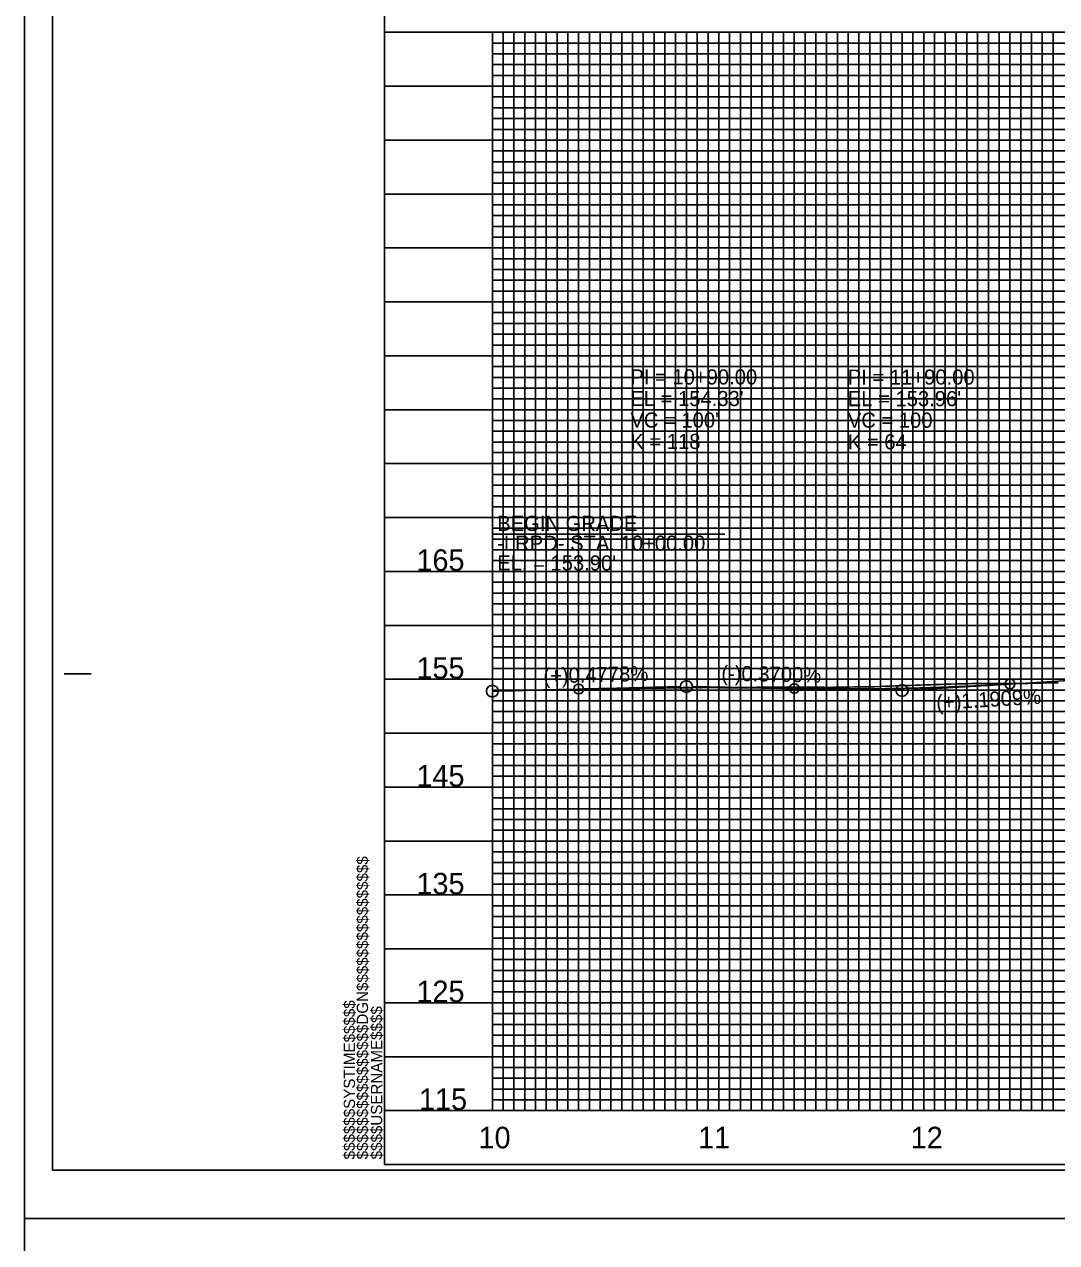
# Model space of a CAD drawing. Extents: x 573468 to 580768, y -57414 to -51768.
# Drawn here: x 578678 to 579157, y -54125 to -53560 of the extents above; entities that cross this region are included whole.
import ezdxf

# ---------------------------------------------------------------- set-up
doc = ezdxf.new("R2010")
doc.units = 0
for name, color, linetype in [('Exist Vertical Profile Ground Line', 7, 'Continuous'), ('Exist Vertical Profile Horizontal Axis Label Major', 7, 'Continuous'), ('Exist Vertical Profile Vertical Axis Label', 7, 'Continuous'), ('Prop Grid Mask', 7, 'Continuous'), ('Prop PFL Text', 7, 'Continuous'), ('Prop Vertical Profile Curve Label', 7, 'Continuous'), ('Prop Vertical Profile Grade', 7, 'Continuous'), ('Prop Vertical Profile Grade Label', 7, 'Continuous'), ('Prop VPI Label', 7, 'Continuous'), ('Sheet Cutting Line CELL', 7, 'Continuous'), ('Sheet DOT Grid CELL', 7, 'Continuous'), ('Sheet Layout Profile Border Port 2', 7, 'Continuous'), ('Sheet Plot Border Inside CELL', 7, 'Continuous'), ('Sheet Plot Border Outside CELL', 7, 'Continuous'), ('Sheet Profile CELL', 7, 'Continuous'), ('Sheet Profile Grid Major CELL', 7, 'Continuous'), ('Sheet Profile Grid Middle CELL', 7, 'Continuous'), ('Sheet Profile Grid Minor CELL', 7, 'Continuous')]:
    doc.layers.add(name, color=color, linetype=linetype)

msp = doc.modelspace()

# ---------------------------------------------------------------- linework, layer by layer
at = {"layer": 'Exist Vertical Profile Ground Line'}
for points in [[(578895.21, -53869.12), (578897.58, -53869.05), (578899.94, -53868.98), (578902.31, -53868.91), (578904.67, -53868.85), (578907.03, -53868.78), (578909.4, -53868.71), (578911.94, -53868.65), (578914.12, -53868.6), (578916.49, -53868.55), (578918.85, -53868.5), (578921.21, -53868.45), (578923.58, -53868.4), (578925.94, -53868.36), (578927.29, -53868.34), (578928.3, -53868.32), (578930.67, -53868.28), (578933.03, -53868.24), (578935.4, -53868.2), (578937.76, -53868.16), (578940.12, -53868.12), (578942.49, -53868.08), (578944.85, -53868.05), (578947.21, -53868.01), (578948.98, -53867.99), (578949.58, -53867.98), (578951.94, -53867.94), (578954.3, -53867.91), (578956.67, -53867.87), (578959.03, -53867.83), (578961.39, -53867.8), (578963.76, -53867.77), (578966.12, -53867.74), (578968.49, -53867.71), (578969.6, -53867.7), (578970.01, -53867.7), (578970.85, -53867.69), (578973.21, -53867.65), (578975.58, -53867.61), (578977.94, -53867.58), (578980.3, -53867.55), (578982.67, -53867.52), (578985.03, -53867.49), (578987.39, -53867.46), (578989.76, -53867.43), (578990.39, -53867.43), (578991.2, -53867.45), (578992.12, -53867.45), (578994.48, -53867.43), (578996.85, -53867.42), (578999.21, -53867.4), (579001.58, -53867.39), (579003.94, -53867.39), (579006.3, -53867.38), (579008.67, -53867.38), (579010.1, -53867.39), (579011.03, -53867.37), (579013.39, -53867.34), (579015.76, -53867.3), (579018.12, -53867.27), (579020.48, -53867.25), (579022.85, -53867.22), (579025.21, -53867.2), (579027.57, -53867.18), (579029.94, -53867.16), (579032.3, -53867.17), (579034.66, -53867.17), (579037.03, -53867.18), (579039.39, -53867.2), (579041.76, -53867.21), (579044.12, -53867.23), (579046.48, -53867.25), (579048.85, -53867.27), (579050.09, -53867.29), (579050.76, -53867.29), (579051.33, -53867.29), (579053.57, -53867.25), (579055.94, -53867.21), (579058.3, -53867.17), (579060.66, -53867.14), (579063.03, -53867.11), (579065.39, -53867.08), (579067.75, -53867.06), (579070.12, -53867.04), (579071.09, -53867.03), (579071.52, -53867.02), (579072.48, -53866.99), (579074.85, -53866.89), (579077.21, -53866.8), (579079.57, -53866.7), (579081.94, -53866.61), (579084.3, -53866.53), (579086.66, -53866.44), (579089.03, -53866.36), (579091.39, -53866.28), (579093.75, -53866.21), (579096.12, -53866.13), (579097.77, -53866.08), (579098.48, -53866.06), (579099.72, -53866.02), (579100.84, -53866.01)], [(579100.84, -53866.01), (579101.17, -53866), (579103.21, -53865.94), (579105.57, -53865.86), (579107.94, -53865.79), (579110.3, -53865.72), (579112.66, -53865.66), (579115.03, -53865.6), (579117.39, -53865.54), (579119.92, -53865.47), (579121.66, -53865.45), (579122.12, -53865.45), (579123.08, -53865.44), (579124.48, -53865.43), (579126.84, -53865.43), (579129.21, -53865.43), (579131.57, -53865.43), (579133.93, -53865.43), (579136.3, -53865.44), (579138.66, -53865.45), (579141.22, -53865.46), (579143.6, -53865.46), (579145.75, -53865.4), (579148.12, -53865.34), (579150.48, -53865.28), (579152.84, -53865.23), (579155.21, -53865.18), (579157.57, -53865.13)]]:
    msp.add_lwpolyline(points, dxfattribs=at)
at = {"layer": 'Prop Grid Mask'}
for points in [[(578945.21, -53713.55), (579045.21, -53713.55), (579045.21, -53763.55), (578945.21, -53763.55)], [(579045.21, -53713.55), (579145.21, -53713.55), (579145.21, -53763.55), (579045.21, -53763.55)]]:
    msp.add_lwpolyline(points, close=True, dxfattribs=at)
at = {"layer": 'Prop PFL Text'}
for q in [(579002.97, -53796.28), (578895.21, -53869.05)]:
    msp.add_line((578895.21, -53796.28), q, dxfattribs=at)
at = {"layer": 'Prop Vertical Profile Curve Label'}
for centre in [(579135.21, -53865.77), (578935.21, -53868.09), (579035.21, -53867.82), (579035.21, -53867.82)]:
    msp.add_circle(centre, 2.25, dxfattribs=at)
at = {"layer": 'Prop Vertical Profile Grade'}
for p, q in [((579135.21, -53865.77), (579195.21, -53862.2)), ((578895.21, -53869.05), (578935.21, -53868.09))]:
    msp.add_line(p, q, dxfattribs=at)
for points in [[(578935.21, -53868.09), (578937.21, -53868.05), (578939.21, -53868), (578941.21, -53867.96), (578943.21, -53867.92), (578945.21, -53867.88), (578947.21, -53867.84), (578949.21, -53867.8), (578951.21, -53867.77), (578953.21, -53867.73), (578955.21, -53867.7), (578957.21, -53867.67), (578959.21, -53867.64), (578961.21, -53867.62), (578963.21, -53867.59), (578965.21, -53867.57), (578967.21, -53867.55), (578969.21, -53867.53), (578971.21, -53867.51), (578973.21, -53867.49), (578975.21, -53867.48), (578977.21, -53867.46), (578979.21, -53867.45), (578981.21, -53867.44), (578983.21, -53867.44), (578985.21, -53867.43), (578987.21, -53867.42), (578989.21, -53867.42), (578991.21, -53867.42), (578993.21, -53867.42), (578995.21, -53867.42), (578997.21, -53867.43), (578999.21, -53867.43), (579001.21, -53867.44), (579003.21, -53867.45), (579005.21, -53867.46), (579007.21, -53867.47), (579009.21, -53867.49), (579011.21, -53867.5), (579013.21, -53867.52), (579015.21, -53867.54), (579017.21, -53867.56), (579019.21, -53867.58), (579021.21, -53867.61), (579023.21, -53867.63), (579025.21, -53867.66), (579027.21, -53867.69), (579029.21, -53867.72), (579031.21, -53867.75), (579033.21, -53867.79), (579035.21, -53867.82)], [(579035.21, -53867.82), (579037.21, -53867.86), (579039.21, -53867.89), (579041.21, -53867.92), (579043.21, -53867.95), (579045.21, -53867.97), (579047.21, -53867.99), (579049.21, -53868.01), (579051.21, -53868.02), (579053.21, -53868.03), (579055.21, -53868.04), (579057.21, -53868.04), (579059.21, -53868.04), (579061.21, -53868.04), (579063.21, -53868.04), (579065.21, -53868.03), (579067.21, -53868.02), (579069.21, -53868), (579071.21, -53867.98), (579073.21, -53867.96), (579075.21, -53867.94), (579077.21, -53867.91), (579079.21, -53867.88), (579081.21, -53867.85), (579083.21, -53867.81), (579085.21, -53867.77), (579087.21, -53867.73), (579089.21, -53867.69), (579091.21, -53867.64), (579093.21, -53867.58), (579095.21, -53867.53), (579097.21, -53867.47), (579099.21, -53867.41), (579101.21, -53867.35), (579103.21, -53867.28), (579105.21, -53867.21), (579107.21, -53867.13), (579109.21, -53867.06), (579111.21, -53866.98), (579113.21, -53866.89), (579115.21, -53866.81), (579117.21, -53866.72), (579119.21, -53866.63), (579121.21, -53866.53), (579123.21, -53866.43), (579125.21, -53866.33), (579127.21, -53866.22), (579129.21, -53866.12), (579131.21, -53866), (579133.21, -53865.89), (579135.21, -53865.77)]]:
    msp.add_spline(points, degree=3, dxfattribs=at)
at = {"layer": 'Prop VPI Label'}
for p, q in [((578935.21, -53868.09), (578982.47, -53866.97)), ((579035.21, -53867.82), (578987.96, -53866.95)), ((579035.21, -53867.82), (579082.47, -53868.7)), ((579135.21, -53865.77), (579087.96, -53868.59))]:
    msp.add_line(p, q, dxfattribs=at)
for centre in [(578895.21, -53869.05), (578985.21, -53866.9), (579085.21, -53868.75)]:
    msp.add_circle(centre, 2.75, dxfattribs=at)
at = {"layer": 'Sheet Cutting Line CELL'}
for p, q in [((578678.21, -53013.55), (578678.21, -54113.55)), ((578678.21, -54113.55), (580362.21, -54113.55)), ((580362.21, -54113.55), (578678.21, -54113.55)), ((578678.21, -54113.55), (578678.21, -55213.55))]:
    msp.add_line(p, q, dxfattribs=at)
at = {"layer": 'Sheet DOT Grid CELL'}
for p, q in [((578845.21, -53563.55), (580345.1, -53563.55)), ((578895.21, -53563.55), (578895.21, -54063.55)), ((578945.21, -53563.55), (578945.21, -54063.55)), ((578995.21, -53563.55), (578995.21, -54063.55)), ((579045.21, -53563.55), (579045.21, -54063.55)), ((579095.21, -53563.55), (579095.21, -54063.55)), ((579145.21, -53563.55), (579145.21, -54063.55)), ((578845.21, -53613.55), (580345.1, -53613.55)), ((578845.21, -53663.55), (580345.1, -53663.55)), ((578845.21, -53713.55), (580345.1, -53713.55)), ((578845.21, -53763.55), (580345.1, -53763.55)), ((578845.21, -53813.55), (580345.1, -53813.55)), ((578845.21, -53863.55), (580345.1, -53863.55)), ((578845.21, -53913.55), (580345.1, -53913.55)), ((578845.21, -53963.55), (580345.1, -53963.55)), ((578845.21, -54013.55), (580345.1, -54013.55))]:
    msp.add_line(p, q, dxfattribs=at)
at = {"layer": 'Sheet Layout Profile Border Port 2'}
msp.add_lwpolyline([(578895.21, -53563.55), (580295.21, -53563.55), (580295.21, -54063.55), (578895.21, -54063.55)], close=True, dxfattribs=at)
at = {"layer": 'Sheet Plot Border Inside CELL'}
msp.add_lwpolyline([(578691.21, -54091.1), (580357.71, -54091.1), (580357.71, -53036), (578691.21, -53036)], close=True, dxfattribs=at)
at = {"layer": 'Sheet Plot Border Outside CELL'}
for points in [[(578678.21, -54113.55), (580362.21, -54113.55), (580362.21, -53013.55), (578678.21, -53013.55)], [(578678.21, -55213.55), (580362.21, -55213.55), (580362.21, -54113.55), (578678.21, -54113.55)]]:
    msp.add_lwpolyline(points, close=True, dxfattribs=at)
at = {"layer": 'Sheet Profile CELL'}
for p, q in [((578845.21, -53563.55), (580345.21, -53563.55)), ((578696.71, -53861.05), (578709.21, -53861.05)), ((580345.21, -54063.55), (578845.21, -54063.55)), ((578845.21, -54088.55), (580345.21, -54088.55)), ((578845.21, -54088.55), (578845.21, -54088.55)), ((578845.21, -54088.55), (578845.21, -54088.55)), ((578845.21, -54088.55), (578845.21, -54088.55)), ((578845.21, -54088.55), (578845.21, -54088.55)), ((578845.21, -54088.55), (578845.21, -54088.55)), ((578845.21, -54088.55), (578845.21, -54088.55)), ((578845.21, -54088.55), (578845.21, -54088.55))]:
    msp.add_line(p, q, dxfattribs=at)
msp.add_lwpolyline([(580345.21, -53038.55), (578845.21, -53038.55), (578845.21, -54088.55), (580345.21, -54088.55)], close=True, dxfattribs=at)
msp.add_lwpolyline([(578882.71, -54088.55), (578882.71, -54088.55)], dxfattribs=at)
at = {"layer": 'Sheet Profile Grid Major CELL'}
msp.add_line((578845.21, -54063.55), (578845.21, -54063.55), dxfattribs=at)
for points in [[(578895.21, -53563.55), (578895.21, -54063.55), (578945.21, -54063.55), (578945.21, -53563.55), (578995.21, -53563.55), (578995.21, -54063.55), (579045.21, -54063.55), (579045.21, -53563.55), (579095.21, -53563.55), (579095.21, -54063.55), (579145.21, -54063.55), (579145.21, -53563.55), (579195.21, -53563.55), (579195.21, -54063.55), (579245.21, -54063.55), (579245.21, -53563.55), (579295.21, -53563.55), (579295.21, -54063.55), (579345.21, -54063.55), (579345.21, -53563.55), (579395.21, -53563.55), (579395.21, -54063.55), (579445.21, -54063.55)], [(580345.21, -53613.55), (578845.21, -53613.55)], [(580345.21, -53663.55), (578845.21, -53663.55), (578845.21, -53713.55), (580345.21, -53713.55)], [(580345.21, -53763.55), (578845.21, -53763.55), (578845.21, -53813.55), (580345.21, -53813.55)], [(580345.21, -53863.55), (578845.21, -53863.55), (578845.21, -53913.55), (580345.21, -53913.55)], [(580345.21, -53963.55), (578845.21, -53963.55), (578845.21, -53963.55), (578845.21, -54013.55), (580345.21, -54013.55)], [(580345.21, -54063.55), (578845.21, -54063.55)]]:
    msp.add_lwpolyline(points, dxfattribs=at)
at = {"layer": 'Sheet Profile Grid Middle CELL'}
for points in [[(578870.21, -53563.55), (578920.21, -53563.55), (578920.21, -54063.55), (578970.21, -54063.55), (578970.21, -53563.55), (579020.21, -53563.55), (579020.21, -54063.55), (579070.21, -54063.55), (579070.21, -53563.55), (579120.21, -53563.55), (579120.21, -54063.55), (579170.21, -54063.55), (579170.21, -53563.55), (579220.21, -53563.55), (579220.21, -54063.55), (579270.21, -54063.55), (579270.21, -53563.55), (579320.21, -53563.55), (579320.21, -54063.55), (579370.21, -54063.55), (579370.21, -53563.55), (579420.21, -53563.55), (579420.21, -54063.55), (579470.21, -54063.55)], [(578845.21, -53588.55), (580345.21, -53588.55)], [(580345.21, -53638.55), (578845.21, -53638.55), (578845.21, -53688.55), (580345.21, -53688.55)], [(580345.21, -53738.55), (578845.21, -53738.55), (578845.21, -53788.55), (580345.21, -53788.55)], [(580345.21, -53838.55), (578845.21, -53838.55), (578845.21, -53888.55), (580345.21, -53888.55)], [(580345.21, -53938.55), (578845.21, -53938.55), (578845.21, -53988.55), (580345.21, -53988.55)], [(580345.21, -54038.55), (578845.21, -54038.55)]]:
    msp.add_lwpolyline(points, dxfattribs=at)
at = {"layer": 'Sheet Profile Grid Minor CELL'}
for p, q in [((578895.21, -53568.55), (580295.21, -53568.55)), ((580295.21, -53573.55), (578895.21, -53573.55)), ((578895.21, -53578.55), (580295.21, -53578.55)), ((580295.21, -53583.55), (578895.21, -53583.55)), ((578895.21, -53593.55), (580295.21, -53593.55)), ((580295.21, -53598.55), (578895.21, -53598.55)), ((578895.21, -53603.55), (580295.21, -53603.55)), ((580295.21, -53608.55), (578895.21, -53608.55)), ((578895.21, -53618.55), (580295.21, -53618.55)), ((580295.21, -53623.55), (578895.21, -53623.55)), ((578895.21, -53628.55), (580295.21, -53628.55)), ((580295.21, -53633.55), (578895.21, -53633.55)), ((578895.21, -53643.55), (580295.21, -53643.55)), ((580295.21, -53648.55), (578895.21, -53648.55)), ((578895.21, -53653.55), (580295.21, -53653.55)), ((580295.21, -53658.55), (578895.21, -53658.55)), ((578895.21, -53668.55), (580295.21, -53668.55)), ((580295.21, -53673.55), (578895.21, -53673.55)), ((578895.21, -53678.55), (580295.21, -53678.55)), ((580295.21, -53683.55), (578895.21, -53683.55)), ((578895.21, -53693.55), (580295.21, -53693.55)), ((580295.21, -53698.55), (578895.21, -53698.55)), ((578895.21, -53703.55), (580295.21, -53703.55)), ((580295.21, -53708.55), (578895.21, -53708.55)), ((578895.21, -53718.55), (580295.21, -53718.55)), ((580295.21, -53723.55), (578895.21, -53723.55)), ((578895.21, -53728.55), (580295.21, -53728.55)), ((580295.21, -53733.55), (578895.21, -53733.55)), ((578895.21, -53743.55), (580295.21, -53743.55)), ((580295.21, -53748.55), (578895.21, -53748.55)), ((578895.21, -53753.55), (580295.21, -53753.55)), ((580295.21, -53758.55), (578895.21, -53758.4)), ((578895.21, -53768.55), (580295.21, -53768.55)), ((580295.21, -53773.55), (578895.21, -53773.55)), ((578895.21, -53778.55), (580295.21, -53778.55)), ((580295.21, -53783.55), (578895.21, -53783.55)), ((578895.21, -53793.55), (580295.21, -53793.55)), ((580295.21, -53798.55), (578895.21, -53798.55)), ((578895.21, -53803.55), (580295.21, -53803.55)), ((580295.21, -53808.55), (578895.21, -53808.55)), ((578895.21, -53818.55), (580295.21, -53818.55)), ((580295.21, -53823.55), (578895.21, -53823.55)), ((578895.21, -53828.55), (580295.21, -53828.55)), ((580295.21, -53833.55), (578895.21, -53833.55)), ((578895.21, -53843.55), (580295.21, -53843.55)), ((580295.21, -53848.55), (578895.21, -53848.55)), ((578895.21, -53853.55), (580295.21, -53853.55)), ((580295.21, -53858.55), (578895.21, -53858.55)), ((578895.21, -53868.55), (580295.21, -53868.55)), ((580295.21, -53873.55), (578895.21, -53873.55)), ((578895.21, -53878.55), (580295.21, -53878.55)), ((580295.21, -53883.55), (578895.21, -53883.55)), ((578895.21, -53893.55), (580295.21, -53893.55)), ((580295.21, -53898.55), (578895.21, -53898.55)), ((578895.21, -53903.55), (580295.21, -53903.55)), ((580295.21, -53908.55), (578895.21, -53908.55)), ((578895.21, -53918.55), (580295.21, -53918.55)), ((580295.21, -53923.55), (578895.21, -53923.55)), ((578895.21, -53928.55), (580295.21, -53928.55)), ((580295.21, -53933.55), (578895.21, -53933.55)), ((578895.21, -53943.55), (580295.21, -53943.55)), ((580295.21, -53948.55), (578895.21, -53948.55)), ((578895.21, -53953.55), (580295.21, -53953.55)), ((580295.21, -53958.55), (578895.21, -53958.55)), ((578895.21, -53968.55), (580295.21, -53968.55)), ((580295.21, -53973.55), (578895.21, -53973.55)), ((578895.21, -53978.55), (580295.21, -53978.55)), ((580295.21, -53983.55), (578895.21, -53983.55)), ((578895.21, -53993.55), (580295.21, -53993.55)), ((580295.21, -53998.55), (578895.21, -53998.55)), ((578895.21, -54003.55), (580295.21, -54003.55)), ((580295.21, -54008.55), (578895.21, -54008.55)), ((578895.21, -54018.55), (580295.21, -54018.55)), ((580295.21, -54023.55), (578895.21, -54023.55)), ((578895.21, -54028.55), (580295.21, -54028.55)), ((580295.21, -54033.55), (578895.21, -54033.55)), ((578895.21, -54043.55), (580295.21, -54043.55)), ((580295.21, -54048.55), (578895.21, -54048.55)), ((578895.21, -54053.55), (580295.21, -54053.55)), ((578895.21, -54058.55), (580295.21, -54058.55))]:
    msp.add_line(p, q, dxfattribs=at)
for points in [[(578895.21, -53563.55), (578900.21, -53563.55), (578900.21, -54063.55), (578905.21, -54063.55), (578905.21, -53563.55), (578910.21, -53563.55), (578910.21, -54063.55), (578915.21, -54063.55), (578915.21, -53563.55), (578925.21, -53563.55), (578925.21, -54063.55), (578930.21, -54063.55), (578930.21, -53563.55), (578935.21, -53563.55), (578935.21, -54063.55), (578940.21, -54063.55), (578950.21, -54063.55), (578955.21, -54063.55), (578955.21, -53563.55), (578960.21, -53563.55), (578960.21, -54063.55), (578965.21, -54063.55), (578965.21, -53563.55), (578975.21, -53563.55), (578975.21, -54063.55), (578980.21, -54063.55), (578980.21, -53563.55), (578985.21, -53563.55), (578985.21, -54063.55), (578990.21, -54063.55), (578990.21, -53563.55), (579000.21, -53563.55), (579000.21, -54063.55), (579005.21, -54063.55), (579005.21, -53563.55), (579010.21, -53563.55), (579010.21, -54063.55), (579015.21, -54063.55), (579015.21, -53563.55), (579025.21, -53563.55), (579025.21, -54063.55), (579030.21, -54063.55), (579030.21, -53563.55), (579035.21, -53563.55), (579035.21, -54063.55), (579040.21, -54063.55), (579040.21, -53563.55), (579050.21, -53563.55), (579050.21, -54063.55), (579055.21, -54063.55), (579055.21, -53563.55), (579060.21, -53563.55), (579060.21, -54063.55), (579065.21, -54063.55), (579065.21, -53563.55), (579075.21, -53563.55), (579075.21, -54063.55), (579080.21, -54063.55), (579080.21, -53563.55), (579085.21, -53563.55), (579085.21, -54063.55), (579090.21, -54063.55), (579090.21, -53563.55), (579100.21, -53563.55), (579100.21, -54063.55), (579105.21, -54063.55), (579105.21, -53563.55), (579110.21, -53563.55), (579110.21, -54063.55)], [(578940.21, -54063.55), (578940.21, -53563.55), (578950.21, -53563.55), (578950.21, -54063.55)], [(579110.21, -54063.55), (579115.21, -54063.55), (579115.21, -53563.55), (579125.21, -53563.55), (579125.21, -54063.55), (579130.21, -54063.55), (579130.21, -53563.55), (579135.21, -53563.55), (579135.21, -54063.55), (579140.21, -54063.55), (579140.21, -53563.55), (579150.21, -53563.55), (579150.21, -54063.55), (579155.21, -54063.55), (579155.21, -53563.55), (579160.21, -53563.55)]]:
    msp.add_lwpolyline(points, dxfattribs=at)

# ---------------------------------------------------------------- texts
at = {"layer": 'Exist Vertical Profile Horizontal Axis Label Major'}
for s, p in [('10', (578888.8, -54081.05)), ('11', (578990.64, -54081.05)), ('12', (579089.19, -54081.05))]:
    msp.add_text(s, height=10, dxfattribs=at).set_placement(p)
at = {"layer": 'Exist Vertical Profile Vertical Axis Label'}
for s, p in [('165', (578860, -53813.3)), ('155', (578860, -53863.3)), ('145', (578860, -53913.3)), ('135', (578860, -53963.3)), ('125', (578860, -54013.3)), ('115', (578861.2, -54063.3))]:
    msp.add_text(s, height=10, dxfattribs=at).set_placement(p)
at = {"layer": 'Prop PFL Text'}
for s, p in [('BEGIN GRADE', (578897.46, -53794.75)), ('-LRPD- STA. 10+00.00', (578897.46, -53803.93)), ("EL. = 153.90'", (578897.46, -53813.1))]:
    msp.add_text(s, height=7, dxfattribs=at).set_placement(p)
at = {"layer": 'Prop Vertical Profile Curve Label'}
for s, p in [("VC = 100'", (578959.2, -53746.85)), ("VC = 100'", (579060.02, -53746.91)), ('K = 118', (578959.2, -53756.77)), ('K = 64', (579060.02, -53756.95))]:
    msp.add_text(s, height=7, dxfattribs=at).set_placement(p)
at = {"layer": 'Prop Vertical Profile Grade Label'}
for s, rotation, p in [('(+)0.4778%', 1.3685, (578918.94, -53865.48)), ('(-)0.3700%', 358.9401, (579001.34, -53864.2)), ('(+)1.1909%', 3.4077, (579101.24, -53877.81))]:
    msp.add_text(s, height=7, rotation=rotation, dxfattribs=at).set_placement(p)
at = {"layer": 'Prop VPI Label'}
for s, p in [('PI = 10+90.00', (578959.2, -53726.85)), ('PI = 11+90.00', (579060.02, -53726.91)), ("EL = 154.33'", (578959.2, -53736.85)), ("EL = 153.96'", (579060.02, -53736.91))]:
    msp.add_text(s, height=7, dxfattribs=at).set_placement(p)
at = {"layer": 'Sheet Profile CELL'}
for s, p in [('$$$$$$$$$$$$$$$$DGN$$$$$$$$$$$$$$$$', (578837.58, -54086.17)), ('$$$$$$SYSTIME$$$$$', (578831.53, -54086.17)), ('$$$$USERNAME$$$$', (578844.15, -54086.16))]:
    msp.add_text(s, height=5.25, rotation=90, dxfattribs=at).set_placement(p)

doc.saveas('drawing.dxf')
